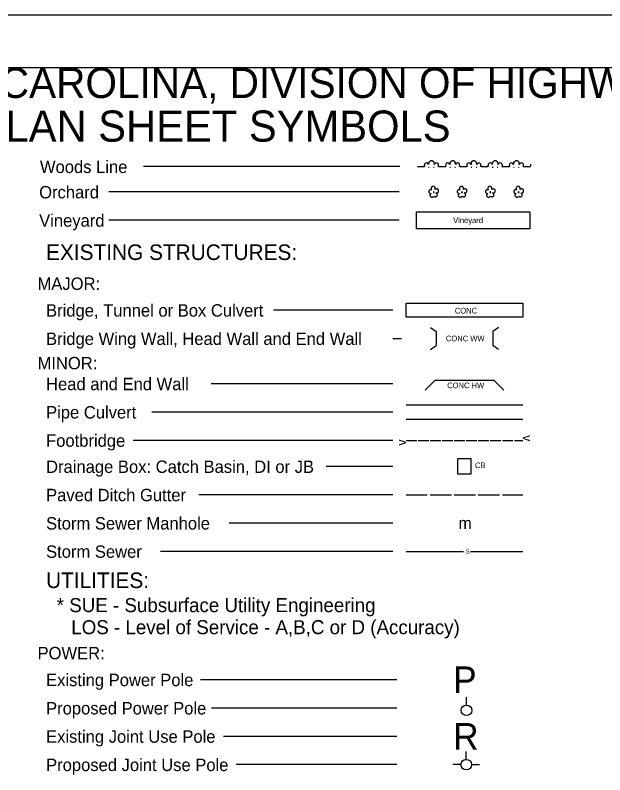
# Model space of a CAD drawing. Extents: x 1855058 to 1858918, y 1540202 to 1542502.
# Drawn here: x 1857985 to 1858405, y 1540760 to 1541302 of the extents above; entities that cross this region are included whole.
import ezdxf

# ---------------------------------------------------------------- set-up
doc = ezdxf.new("R2010")
doc.units = 0
doc.layers.add('CTL Secondary Horizontal and Vertical CELL', color=7, linetype='Continuous')

msp = doc.modelspace()

# ---------------------------------------------------------------- linework, layer by layer
at = {"layer": 'CTL Secondary Horizontal and Vertical CELL'}
for p, q in [((1858818.6, 1541301.77), (1857118.6, 1541301.77)), ((1858781.1, 1541264.27), (1857156.1, 1541264.27)), ((1858258.58, 1541193.83), (1858075.83, 1541193.83)), ((1858271.08, 1541193.83), (1858276.13, 1541193.83)), ((1858279.1, 1541193.33), (1858279.61, 1541193.33)), ((1858282.63, 1541193.33), (1858283.14, 1541193.33)), ((1858286.21, 1541193.83), (1858291.26, 1541193.83)), ((1858294.24, 1541193.33), (1858294.74, 1541193.33)), ((1858297.77, 1541193.33), (1858298.27, 1541193.33)), ((1858301.35, 1541193.83), (1858306.39, 1541193.83)), ((1858309.37, 1541193.33), (1858309.87, 1541193.33)), ((1858312.9, 1541193.33), (1858313.41, 1541193.33)), ((1858316.48, 1541193.83), (1858321.53, 1541193.83)), ((1858324.5, 1541193.33), (1858325.01, 1541193.33)), ((1858328.04, 1541193.33), (1858328.54, 1541193.33)), ((1858331.62, 1541193.83), (1858336.66, 1541193.83)), ((1858339.64, 1541193.33), (1858340.14, 1541193.33)), ((1858343.17, 1541193.33), (1858343.67, 1541193.33)), ((1858346.75, 1541193.83), (1858351.8, 1541193.83)), ((1858258.01, 1541175.74), (1858051.24, 1541175.74)), ((1858258.01, 1541155.56), (1858051.24, 1541155.56)), ((1858253.65, 1541091.49), (1858168.47, 1541091.49)), ((1858280.34, 1541079.24), (1858284.48, 1541076.36)), ((1858284.48, 1541076.36), (1858284.48, 1541066.27)), ((1858328.97, 1541079.24), (1858324.83, 1541076.36)), ((1858324.83, 1541076.36), (1858324.83, 1541066.27)), ((1858253.65, 1541071.31), (1858259.69, 1541071.31)), ((1858280.34, 1541063.38), (1858284.48, 1541066.27)), ((1858328.97, 1541063.38), (1858324.83, 1541066.27)), ((1858276.71, 1541034.42), (1858283.85, 1541041.55)), ((1858283.85, 1541041.55), (1858325.46, 1541041.55)), ((1858325.46, 1541041.55), (1858332.6, 1541034.42)), ((1858253.65, 1541039.03), (1858124.21, 1541039.03)), ((1858263.04, 1541023.9), (1858346.27, 1541023.9)), ((1858253.65, 1541018.85), (1858081.94, 1541018.85)), ((1858263.04, 1541013.81), (1858346.27, 1541013.81)), ((1858253.65, 1540998.67), (1858068.54, 1540998.67)), ((1858263.04, 1540998.67), (1858270.6, 1540998.67)), ((1858271.61, 1540998.67), (1858279.18, 1540998.67)), ((1858280.19, 1540998.67), (1858287.76, 1540998.67)), ((1858288.76, 1540998.67), (1858296.33, 1540998.67)), ((1858297.34, 1540998.67), (1858304.91, 1540998.67)), ((1858305.92, 1540998.67), (1858313.48, 1540998.67)), ((1858314.49, 1540998.67), (1858322.06, 1540998.67)), ((1858323.07, 1540998.67), (1858330.64, 1540998.67)), ((1858331.64, 1540998.67), (1858339.21, 1540998.67)), ((1858340.22, 1540998.67), (1858346.27, 1540998.67)), ((1858253.65, 1540980.07), (1858206.03, 1540980.07)), ((1858253.65, 1540959.89), (1858115.48, 1540959.89)), ((1858263.04, 1540959.89), (1858278.17, 1540959.89)), ((1858280.19, 1540959.89), (1858295.32, 1540959.89)), ((1858297.34, 1540959.89), (1858312.47, 1540959.89)), ((1858314.49, 1540959.89), (1858329.63, 1540959.89)), ((1858331.64, 1540959.89), (1858346.27, 1540959.89)), ((1858253.65, 1540939.72), (1858136.94, 1540939.72)), ((1858253.65, 1540919.54), (1858087.99, 1540919.54)), ((1858263.04, 1540919.54), (1858303.92, 1540919.54)), ((1858308.97, 1540919.54), (1858346.27, 1540919.54)), ((1858256.47, 1540828.04), (1858116.53, 1540828.04)), ((1858306.13, 1540810), (1858306.13, 1540815.67)), ((1858256.47, 1540807.87), (1858124.38, 1540807.87)), ((1858256.47, 1540787.69), (1858132.86, 1540787.69)), ((1858305.92, 1540771.3), (1858305.92, 1540776.98)), ((1858256.47, 1540767.51), (1858141.94, 1540767.51)), ((1858302.13, 1540767.52), (1858296.46, 1540767.52)), ((1858309.7, 1540767.52), (1858315.37, 1540767.52))]:
    msp.add_line(p, q, dxfattribs=at)
for points in [[(1858283.68, 1541177.51), (1858283.83, 1541177.81), (1858283.88, 1541178.11), (1858283.83, 1541178.42), (1858283.78, 1541178.72), (1858283.63, 1541178.97), (1858283.48, 1541179.22), (1858283.22, 1541179.43), (1858282.97, 1541179.58), (1858282.62, 1541179.68), (1858282.37, 1541179.68), (1858282.06, 1541179.63), (1858281.76, 1541179.53), (1858281.51, 1541179.38), (1858281.26, 1541179.17), (1858281.1, 1541178.87), (1858281, 1541178.62), (1858280.95, 1541178.32), (1858280.95, 1541178.01), (1858281, 1541177.71), (1858281.15, 1541177.46), (1858281.36, 1541177.16), (1858281.1, 1541177.31), (1858280.8, 1541177.36), (1858280.5, 1541177.36), (1858280.25, 1541177.26), (1858279.99, 1541177.16), (1858279.74, 1541176.95), (1858279.54, 1541176.75), (1858279.39, 1541176.5), (1858279.34, 1541176.25), (1858279.29, 1541175.89), (1858279.34, 1541175.64), (1858279.44, 1541175.39), (1858279.64, 1541175.14), (1858279.79, 1541174.94), (1858280.04, 1541174.78), (1858280.35, 1541174.63), (1858280.6, 1541174.58), (1858280.9, 1541174.58), (1858280.65, 1541174.48), (1858280.4, 1541174.28), (1858280.25, 1541174.08), (1858280.15, 1541173.78), (1858280.04, 1541173.47), (1858280.04, 1541173.22), (1858280.1, 1541172.92), (1858280.25, 1541172.67), (1858280.4, 1541172.41), (1858280.6, 1541172.21), (1858280.85, 1541172.06), (1858281.1, 1541171.96), (1858281.41, 1541171.96), (1858281.71, 1541171.96), (1858281.96, 1541172.01), (1858282.21, 1541172.21), (1858282.47, 1541172.36), (1858282.72, 1541172.82)], [(1858282.72, 1541172.82), (1858283.32, 1541172.46), (1858283.63, 1541172.36), (1858283.93, 1541172.31), (1858284.23, 1541172.36), (1858284.48, 1541172.46), (1858284.74, 1541172.62), (1858284.99, 1541172.82), (1858285.14, 1541173.07), (1858285.24, 1541173.32), (1858285.34, 1541173.62), (1858285.29, 1541173.93), (1858285.24, 1541174.23), (1858285.04, 1541174.53), (1858284.89, 1541174.73), (1858284.64, 1541174.89), (1858284.33, 1541175.04), (1858284.64, 1541174.99), (1858284.99, 1541174.99), (1858285.24, 1541175.09), (1858285.54, 1541175.24), (1858285.8, 1541175.39), (1858286, 1541175.64), (1858286.15, 1541175.94), (1858286.2, 1541176.25), (1858286.25, 1541176.55), (1858286.2, 1541176.85), (1858286.1, 1541177.16), (1858285.9, 1541177.41), (1858285.64, 1541177.66), (1858285.39, 1541177.81), (1858285.09, 1541177.91), (1858284.79, 1541177.96), (1858284.48, 1541177.96), (1858284.18, 1541177.86), (1858283.93, 1541177.71), (1858283.68, 1541177.51)], [(1858303.86, 1541177.51), (1858304.01, 1541177.81), (1858304.06, 1541178.11), (1858304.01, 1541178.42), (1858303.96, 1541178.72), (1858303.81, 1541178.97), (1858303.65, 1541179.22), (1858303.4, 1541179.43), (1858303.15, 1541179.58), (1858302.8, 1541179.68), (1858302.54, 1541179.68), (1858302.24, 1541179.63), (1858301.94, 1541179.53), (1858301.69, 1541179.38), (1858301.43, 1541179.17), (1858301.28, 1541178.87), (1858301.18, 1541178.62), (1858301.13, 1541178.32), (1858301.13, 1541178.01), (1858301.18, 1541177.71), (1858301.33, 1541177.46), (1858301.54, 1541177.16), (1858301.28, 1541177.31), (1858300.98, 1541177.36), (1858300.68, 1541177.36), (1858300.43, 1541177.26), (1858300.17, 1541177.16), (1858299.92, 1541176.95), (1858299.72, 1541176.75), (1858299.57, 1541176.5), (1858299.52, 1541176.25), (1858299.47, 1541175.89), (1858299.52, 1541175.64), (1858299.62, 1541175.39), (1858299.82, 1541175.14), (1858299.97, 1541174.94), (1858300.22, 1541174.78), (1858300.53, 1541174.63), (1858300.78, 1541174.58), (1858301.08, 1541174.58), (1858300.83, 1541174.48), (1858300.58, 1541174.28), (1858300.43, 1541174.08), (1858300.32, 1541173.78), (1858300.22, 1541173.47), (1858300.22, 1541173.22), (1858300.27, 1541172.92), (1858300.43, 1541172.67), (1858300.58, 1541172.41), (1858300.78, 1541172.21), (1858301.03, 1541172.06), (1858301.28, 1541171.96), (1858301.59, 1541171.96), (1858301.89, 1541171.96), (1858302.14, 1541172.01), (1858302.39, 1541172.21), (1858302.65, 1541172.36), (1858302.9, 1541172.82)], [(1858302.9, 1541172.82), (1858303.5, 1541172.46), (1858303.81, 1541172.36), (1858304.11, 1541172.31), (1858304.41, 1541172.36), (1858304.66, 1541172.46), (1858304.92, 1541172.62), (1858305.17, 1541172.82), (1858305.32, 1541173.07), (1858305.42, 1541173.32), (1858305.52, 1541173.62), (1858305.47, 1541173.93), (1858305.42, 1541174.23), (1858305.22, 1541174.53), (1858305.07, 1541174.73), (1858304.81, 1541174.89), (1858304.51, 1541175.04), (1858304.81, 1541174.99), (1858305.17, 1541174.99), (1858305.42, 1541175.09), (1858305.72, 1541175.24), (1858305.97, 1541175.39), (1858306.18, 1541175.64), (1858306.33, 1541175.94), (1858306.38, 1541176.25), (1858306.43, 1541176.55), (1858306.38, 1541176.85), (1858306.28, 1541177.16), (1858306.08, 1541177.41), (1858305.82, 1541177.66), (1858305.57, 1541177.81), (1858305.27, 1541177.91), (1858304.97, 1541177.96), (1858304.66, 1541177.96), (1858304.36, 1541177.86), (1858304.11, 1541177.71), (1858303.86, 1541177.51)], [(1858324.03, 1541177.51), (1858324.19, 1541177.81), (1858324.24, 1541178.11), (1858324.19, 1541178.42), (1858324.14, 1541178.72), (1858323.98, 1541178.97), (1858323.83, 1541179.22), (1858323.58, 1541179.43), (1858323.33, 1541179.58), (1858322.98, 1541179.68), (1858322.72, 1541179.68), (1858322.42, 1541179.63), (1858322.12, 1541179.53), (1858321.87, 1541179.38), (1858321.61, 1541179.17), (1858321.46, 1541178.87), (1858321.36, 1541178.62), (1858321.31, 1541178.32), (1858321.31, 1541178.01), (1858321.36, 1541177.71), (1858321.51, 1541177.46), (1858321.71, 1541177.16), (1858321.46, 1541177.31), (1858321.16, 1541177.36), (1858320.86, 1541177.36), (1858320.6, 1541177.26), (1858320.35, 1541177.16), (1858320.1, 1541176.95), (1858319.9, 1541176.75), (1858319.75, 1541176.5), (1858319.7, 1541176.25), (1858319.65, 1541175.89), (1858319.7, 1541175.64), (1858319.8, 1541175.39), (1858320, 1541175.14), (1858320.15, 1541174.94), (1858320.4, 1541174.78), (1858320.71, 1541174.63), (1858320.96, 1541174.58), (1858321.26, 1541174.58), (1858321.01, 1541174.48), (1858320.76, 1541174.28), (1858320.6, 1541174.08), (1858320.5, 1541173.78), (1858320.4, 1541173.47), (1858320.4, 1541173.22), (1858320.45, 1541172.92), (1858320.6, 1541172.67), (1858320.76, 1541172.41), (1858320.96, 1541172.21), (1858321.21, 1541172.06), (1858321.46, 1541171.96), (1858321.76, 1541171.96), (1858322.07, 1541171.96), (1858322.32, 1541172.01), (1858322.57, 1541172.21), (1858322.82, 1541172.36), (1858323.08, 1541172.82)], [(1858323.08, 1541172.82), (1858323.68, 1541172.46), (1858323.98, 1541172.36), (1858324.29, 1541172.31), (1858324.59, 1541172.36), (1858324.84, 1541172.46), (1858325.09, 1541172.62), (1858325.35, 1541172.82), (1858325.5, 1541173.07), (1858325.6, 1541173.32), (1858325.7, 1541173.62), (1858325.65, 1541173.93), (1858325.6, 1541174.23), (1858325.4, 1541174.53), (1858325.25, 1541174.73), (1858324.99, 1541174.89), (1858324.69, 1541175.04), (1858324.99, 1541174.99), (1858325.35, 1541174.99), (1858325.6, 1541175.09), (1858325.9, 1541175.24), (1858326.15, 1541175.39), (1858326.36, 1541175.64), (1858326.51, 1541175.94), (1858326.56, 1541176.25), (1858326.61, 1541176.55), (1858326.56, 1541176.85), (1858326.46, 1541177.16), (1858326.25, 1541177.41), (1858326, 1541177.66), (1858325.75, 1541177.81), (1858325.45, 1541177.91), (1858325.14, 1541177.96), (1858324.84, 1541177.96), (1858324.54, 1541177.86), (1858324.29, 1541177.71), (1858324.03, 1541177.51)], [(1858344.21, 1541177.51), (1858344.36, 1541177.81), (1858344.42, 1541178.11), (1858344.36, 1541178.42), (1858344.31, 1541178.72), (1858344.16, 1541178.97), (1858344.01, 1541179.22), (1858343.76, 1541179.43), (1858343.51, 1541179.58), (1858343.15, 1541179.68), (1858342.9, 1541179.68), (1858342.6, 1541179.63), (1858342.3, 1541179.53), (1858342.04, 1541179.38), (1858341.79, 1541179.17), (1858341.64, 1541178.87), (1858341.54, 1541178.62), (1858341.49, 1541178.32), (1858341.49, 1541178.01), (1858341.54, 1541177.71), (1858341.69, 1541177.46), (1858341.89, 1541177.16), (1858341.64, 1541177.31), (1858341.34, 1541177.36), (1858341.04, 1541177.36), (1858340.78, 1541177.26), (1858340.53, 1541177.16), (1858340.28, 1541176.95), (1858340.08, 1541176.75), (1858339.93, 1541176.5), (1858339.88, 1541176.25), (1858339.82, 1541175.89), (1858339.88, 1541175.64), (1858339.98, 1541175.39), (1858340.18, 1541175.14), (1858340.33, 1541174.94), (1858340.58, 1541174.78), (1858340.88, 1541174.63), (1858341.14, 1541174.58), (1858341.44, 1541174.58), (1858341.19, 1541174.48), (1858340.93, 1541174.28), (1858340.78, 1541174.08), (1858340.68, 1541173.78), (1858340.58, 1541173.47), (1858340.58, 1541173.22), (1858340.63, 1541172.92), (1858340.78, 1541172.67), (1858340.93, 1541172.41), (1858341.14, 1541172.21), (1858341.39, 1541172.06), (1858341.64, 1541171.96), (1858341.94, 1541171.96), (1858342.25, 1541171.96), (1858342.5, 1541172.01), (1858342.75, 1541172.21), (1858343, 1541172.36), (1858343.25, 1541172.82)], [(1858343.25, 1541172.82), (1858343.86, 1541172.46), (1858344.16, 1541172.36), (1858344.47, 1541172.31), (1858344.77, 1541172.36), (1858345.02, 1541172.46), (1858345.27, 1541172.62), (1858345.53, 1541172.82), (1858345.68, 1541173.07), (1858345.78, 1541173.32), (1858345.88, 1541173.62), (1858345.83, 1541173.93), (1858345.78, 1541174.23), (1858345.58, 1541174.53), (1858345.42, 1541174.73), (1858345.17, 1541174.89), (1858344.87, 1541175.04), (1858345.17, 1541174.99), (1858345.53, 1541174.99), (1858345.78, 1541175.09), (1858346.08, 1541175.24), (1858346.33, 1541175.39), (1858346.53, 1541175.64), (1858346.69, 1541175.94), (1858346.74, 1541176.25), (1858346.79, 1541176.55), (1858346.74, 1541176.85), (1858346.63, 1541177.16), (1858346.43, 1541177.41), (1858346.18, 1541177.66), (1858345.93, 1541177.81), (1858345.63, 1541177.91), (1858345.32, 1541177.96), (1858345.02, 1541177.96), (1858344.72, 1541177.86), (1858344.47, 1541177.71), (1858344.21, 1541177.51)], [(1858282.82, 1541175.74), (1858282.67, 1541175.74), (1858282.57, 1541175.69), (1858282.47, 1541175.64), (1858282.47, 1541175.49), (1858282.47, 1541175.39), (1858282.57, 1541175.29), (1858282.72, 1541175.29), (1858282.82, 1541175.29), (1858282.92, 1541175.39), (1858282.97, 1541175.54), (1858282.92, 1541175.64), (1858282.82, 1541175.74)], [(1858303, 1541175.74), (1858302.85, 1541175.74), (1858302.75, 1541175.69), (1858302.65, 1541175.64), (1858302.65, 1541175.49), (1858302.65, 1541175.39), (1858302.75, 1541175.29), (1858302.9, 1541175.29), (1858303, 1541175.29), (1858303.1, 1541175.39), (1858303.15, 1541175.54), (1858303.1, 1541175.64), (1858303, 1541175.74)], [(1858323.18, 1541175.74), (1858323.03, 1541175.74), (1858322.92, 1541175.69), (1858322.82, 1541175.64), (1858322.82, 1541175.49), (1858322.82, 1541175.39), (1858322.92, 1541175.29), (1858323.08, 1541175.29), (1858323.18, 1541175.29), (1858323.28, 1541175.39), (1858323.33, 1541175.54), (1858323.28, 1541175.64), (1858323.18, 1541175.74)], [(1858343.36, 1541175.74), (1858343.2, 1541175.74), (1858343.1, 1541175.69), (1858343, 1541175.64), (1858343, 1541175.49), (1858343, 1541175.39), (1858343.1, 1541175.29), (1858343.25, 1541175.29), (1858343.36, 1541175.29), (1858343.46, 1541175.39), (1858343.51, 1541175.54), (1858343.46, 1541175.64), (1858343.36, 1541175.74)], [(1858270.51, 1541161.62), (1858351.23, 1541161.62), (1858351.23, 1541149.51), (1858270.51, 1541149.51), (1858270.51, 1541161.62)], [(1858263.04, 1541096.54), (1858346.27, 1541096.54), (1858346.27, 1541086.45), (1858263.04, 1541086.45), (1858263.04, 1541096.54)]]:
    msp.add_lwpolyline(points, dxfattribs=at)
msp.add_lwpolyline([(1858299.8, 1540974.71), (1858309.5, 1540974.71), (1858309.5, 1540985.45), (1858299.8, 1540985.45)], close=True, dxfattribs=at)
for centre in [(1858306.13, 1540806.21), (1858305.92, 1540767.51)]:
    msp.add_circle(centre, 3.78, dxfattribs=at)
for centre, radius, start, end in [((1858277.59, 1541194.85), 1.6, 18.435, 219.2315), ((1858281.12, 1541195.86), 2.08, 345.9638, 194.0362), ((1858284.65, 1541194.85), 1.6, 320.7685, 161.5651), ((1858292.72, 1541194.85), 1.6, 18.435, 219.2315), ((1858296.25, 1541195.86), 2.08, 345.9638, 194.0362), ((1858299.78, 1541194.85), 1.6, 320.7685, 161.5651), ((1858307.85, 1541194.85), 1.6, 18.435, 219.2315), ((1858311.39, 1541195.86), 2.08, 345.9638, 194.0362), ((1858314.92, 1541194.85), 1.6, 320.7685, 161.5651), ((1858322.99, 1541194.85), 1.6, 18.435, 219.2315), ((1858326.52, 1541195.86), 2.08, 345.9638, 194.0362), ((1858330.05, 1541194.85), 1.6, 320.7685, 161.5651), ((1858338.12, 1541194.85), 1.6, 18.435, 219.2315), ((1858341.65, 1541195.86), 2.08, 345.9638, 194.0362), ((1858345.18, 1541194.85), 1.6, 320.7685, 161.5651), ((1858353.26, 1541194.85), 1.6, 156.251, 203.749)]:
    msp.add_arc(centre, radius, start, end, dxfattribs=at)

# ---------------------------------------------------------------- texts
for s, height, p in [('STATE OF NORTH CAROLINA, DIVISION OF HIGHWAYS', 21.6104, (1857713.46, 1541242.74)), ('CONVENTIONAL  PLAN SHEET SYMBOLS', 22.2292, (1857706.7, 1541211.58)), ('Woods Line', 8.828, (1858002.14, 1541189.26)), ('Orchard', 8.828, (1858001.57, 1541171.18)), ('Vineyard', 8.828, (1858001.57, 1541151)), ('EXISTING STRUCTURES:', 11.0983, (1858006.5, 1541127.26)), ('MAJOR:', 8.828, (1858000.42, 1541105.96)), ('Bridge, Tunnel or Box Culvert', 8.8282, (1858006.5, 1541086.9)), ('CONC', 4.036, (1858297.78, 1541089.11)), ('Bridge Wing Wall, Head Wall and End Wall', 8.8282, (1858006.5, 1541066.72)), ('MINOR:', 8.828, (1858000.42, 1541049.33)), ('Head and End Wall', 8.8282, (1858006.5, 1541034.44)), ('CONC HW', 4.036, (1858292.35, 1541035.84)), ('Pipe Culvert', 8.8282, (1858006.5, 1541014.27)), ('Footbridge', 8.828, (1858006.51, 1540994.1)), ('Drainage Box: Catch Basin, DI or JB', 8.8282, (1858006.51, 1540975.49)), ('CB', 4.036, (1858312.16, 1540978.89)), ('Paved Ditch Gutter', 8.8282, (1858006.51, 1540955.3)), ('Storm Sewer Manhole', 8.8282, (1858006.51, 1540935.12)), ('m', 8.32, (1858300.49, 1540935.55)), ('Storm Sewer', 8.8282, (1858006.51, 1540914.95)), ('S', 3.03, (1858305.54, 1540918.02)), ('UTILITIES:', 11.098, (1858006.5, 1540893.39)), ('* SUE - Subsurface Utility Engineering', 9.9885, (1858014.11, 1540876.22)), ('LOS - Level of Service - A,B,C or D (Accuracy) ', 9.9885, (1858024.46, 1540860.51)), ('POWER:', 8.828, (1858000.42, 1540842.64)), ('P', 18.92, (1858296.46, 1540818.59)), ('Existing Power Pole', 8.8282, (1858006.51, 1540823.47)), ('Proposed Power Pole', 8.8282, (1858006.51, 1540803.29)), ('Existing Joint Use Pole', 8.8282, (1858006.51, 1540783.12)), ('R', 18.92, (1858296.46, 1540778.23)), ('Proposed Joint Use Pole', 8.8282, (1858006.53, 1540762.93))]:
    msp.add_text(s, height=height, dxfattribs=at).set_placement(p)
for s, height, rotation, p in [('Vineyard', 4.036, 0, (1858296.57, 1541153.55)), ('CONC WW', 4.036, 0, (1858291.41, 1541069.29)), ('v', 6.66, 89.7591, (1858263.02, 1540994.9)), ('v', 6.66, 270.2409, (1858346.26, 1541002.44))]:
    msp.add_text(s, height=height, rotation=rotation, dxfattribs=at).set_placement(p)

doc.saveas('drawing.dxf')
